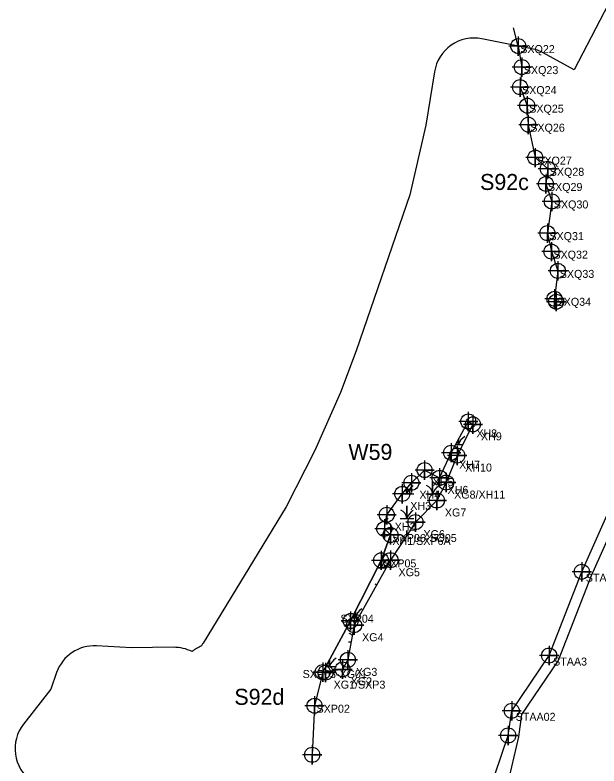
# Model space of a CAD drawing. Extents: x 1253697 to 1278588, y 912189 to 981699.
# Drawn here: x 1253847 to 1254577, y 954967 to 955905 of the extents above; entities that cross this region are included whole.
import ezdxf

# ---------------------------------------------------------------- set-up
doc = ezdxf.new("R2010")
doc.units = 0
for name, color, linetype in [('Default', 7, 'Continuous'), ('Exist Environmental Wetland Boundary', 7, 'Continuous'), ('Exist Environmental Wetland Boundary Cogo Comment', 7, 'Continuous'), ('Exist Environmental Wetland Boundary Cogo Number', 7, 'Continuous'), ('Exist Environmental Wetland Boundary Cogo Point CELL', 7, 'Continuous'), ('Exist Hydro Jurisdictional Stream or Body of Water Mitigable', 7, 'Continuous'), ('Exist Hydro Jurisdictional Stream or Body of Water Mitigable Cogo Comment', 7, 'Continuous'), ('Exist Hydro Jurisdictional Stream or Body of Water Mitigable Cogo Number', 7, 'Continuous'), ('Exist Hydro Jurisdictional Stream or Body of Water Mitigable Cogo Point CELL', 7, 'Continuous'), ('Exist Hydro Swamp or Marsh', 7, 'Continuous')]:
    doc.layers.add(name, color=color, linetype=linetype)

msp = doc.modelspace()

# ---------------------------------------------------------------- linework, layer by layer
at = {"layer": 'Default'}
msp.add_line((1254492.86, 955862.86), (1254430.48, 955875.23), dxfattribs=at)
msp.add_line((1254492.86, 955862.86), (1254430.48, 955875.23), dxfattribs=at)
for points in [[(1254696.64, 956137.98), (1254679.34, 956093.11), (1254545.8, 955836.6), (1254507.05, 955857.72)], [(1254696.64, 956137.98), (1254679.34, 956093.11), (1254545.8, 955836.6), (1254507.05, 955857.72)], [(1254371.38, 955834.12), (1254360.65, 955767.27), (1254340.62, 955680.3), (1254273.47, 955485.55), (1254253.73, 955433.3), (1254221.57, 955360.82), (1254186.04, 955290.67), (1254082.07, 955120.37)], [(1254371.38, 955834.12), (1254360.65, 955767.27), (1254340.62, 955680.3), (1254273.47, 955485.55), (1254253.73, 955433.3), (1254221.57, 955360.82), (1254186.04, 955290.67), (1254082.07, 955120.37)], [(1254045.19, 955115.2), (1253992.76, 955114.66), (1253948.91, 955117.02)], [(1254045.19, 955115.2), (1253992.76, 955114.66), (1253948.91, 955117.02)], [(1253899.08, 955083.78), (1253891.75, 955063.05), (1253857.58, 955019.14)], [(1253899.08, 955083.78), (1253891.75, 955063.05), (1253857.58, 955019.14)]]:
    msp.add_lwpolyline(points, dxfattribs=at)
for centre, start, end in [((1254420.75, 955826.19), 78.77842, 170.8771), ((1254420.75, 955826.19), 78.77842, 170.8771), ((1254483.12, 955813.81), 61.41368, 78.77842), ((1254483.12, 955813.81), 61.41368, 78.77842), ((1253946.22, 955067.1), 86.9118, 160.51196), ((1253946.22, 955067.1), 86.9118, 160.51196), ((1254099.89, 955071.01), 113.22247, 129.13537), ((1254099.89, 955071.01), 113.22247, 129.13537), ((1254124.75, 955094.31), 148.59736, 153.07059), ((1254124.75, 955094.31), 148.59736, 153.07059), ((1254045.7, 955065.2), 63.09678, 90.5931), ((1254045.7, 955065.2), 63.09678, 90.5931), ((1253897.05, 954988.44), 142.11777, 233.22043), ((1253897.05, 954988.44), 142.11777, 233.22043)]:
    msp.add_arc(centre, 50, start, end, dxfattribs=at)
at = {"layer": 'Exist Environmental Wetland Boundary'}
for points in [[(1254308.65, 955263.05), (1254311.59, 955280.74), (1254331.04, 955306.85), (1254342.46, 955320.63), (1254359.01, 955336.53), (1254377.65, 955326.81), (1254392.11, 955358.23), (1254413.55, 955397.26), (1254419.41, 955393.67), (1254399.65, 955354.73), (1254385.85, 955320.93), (1254374.25, 955298.6), (1254347.55, 955271.5), (1254316.35, 955223.95), (1254270.84, 955142.78), (1254263.09, 955099.51), (1254256.48, 955087.62), (1254231.58, 955084.16)], [(1254231.58, 955084.16), (1254266.5, 955148.05), (1254304.54, 955223.8), (1254316.31, 955255.48), (1254308.65, 955263.05)]]:
    msp.add_lwpolyline(points, dxfattribs=at)
at = {"layer": 'Exist Environmental Wetland Boundary Cogo Point CELL'}
for points in [[(1254413.55, 955409.26), (1254413.55, 955385.26), (1254413.55, 955397.26), (1254425.55, 955397.26), (1254401.55, 955397.26)], [(1254419.41, 955405.67), (1254419.41, 955381.67), (1254419.41, 955393.67), (1254431.41, 955393.67), (1254407.41, 955393.67)], [(1254392.11, 955370.23), (1254392.11, 955346.23), (1254392.11, 955358.23), (1254404.11, 955358.23), (1254380.11, 955358.23)], [(1254399.65, 955366.74), (1254399.65, 955342.74), (1254399.65, 955354.73), (1254411.65, 955354.73), (1254387.65, 955354.73)], [(1254359.01, 955348.53), (1254359.01, 955324.53), (1254359.01, 955336.53), (1254371.01, 955336.53), (1254347.01, 955336.53)], [(1254342.46, 955332.63), (1254342.46, 955308.63), (1254342.46, 955320.63), (1254354.46, 955320.63), (1254330.46, 955320.63)], [(1254377.65, 955338.81), (1254377.65, 955314.81), (1254377.65, 955326.81), (1254389.65, 955326.81), (1254365.65, 955326.81)], [(1254385.85, 955332.93), (1254385.85, 955308.93), (1254385.85, 955320.93), (1254397.85, 955320.93), (1254373.85, 955320.93)], [(1254331.04, 955318.85), (1254331.04, 955294.85), (1254331.04, 955306.85), (1254343.04, 955306.85), (1254319.04, 955306.85)], [(1254374.25, 955310.6), (1254374.25, 955286.6), (1254374.25, 955298.6), (1254386.25, 955298.6), (1254362.25, 955298.6)], [(1254311.59, 955292.74), (1254311.59, 955268.74), (1254311.59, 955280.74), (1254323.59, 955280.74), (1254299.59, 955280.74)], [(1254347.55, 955283.5), (1254347.55, 955259.5), (1254347.55, 955271.5), (1254359.55, 955271.5), (1254335.55, 955271.5)], [(1254308.65, 955275.05), (1254308.65, 955251.05), (1254308.65, 955263.05), (1254320.65, 955263.05), (1254296.65, 955263.05)], [(1254316.35, 955235.95), (1254316.35, 955211.95), (1254316.35, 955223.95), (1254328.35, 955223.95), (1254304.35, 955223.95)], [(1254270.84, 955154.78), (1254270.84, 955130.78), (1254270.84, 955142.78), (1254282.84, 955142.78), (1254258.84, 955142.78)], [(1254263.09, 955111.51), (1254263.09, 955087.51), (1254263.09, 955099.51), (1254275.09, 955099.51), (1254251.09, 955099.51)], [(1254256.48, 955099.62), (1254256.48, 955075.62), (1254256.48, 955087.62), (1254268.48, 955087.62), (1254244.48, 955087.62)], [(1254235.27, 955095.59), (1254235.27, 955071.59), (1254235.27, 955083.59), (1254247.27, 955083.59), (1254223.27, 955083.59)]]:
    msp.add_lwpolyline(points, dxfattribs=at)
for centre in [(1254413.55, 955397.26), (1254419.41, 955393.67), (1254392.11, 955358.23), (1254399.65, 955354.73), (1254359.01, 955336.53), (1254377.65, 955326.81), (1254342.46, 955320.63), (1254385.85, 955320.93), (1254331.04, 955306.85), (1254374.25, 955298.6), (1254311.59, 955280.74), (1254347.55, 955271.5), (1254308.65, 955263.05), (1254316.35, 955223.95), (1254270.84, 955142.78), (1254263.09, 955099.51), (1254256.48, 955087.62), (1254235.27, 955083.59)]:
    msp.add_circle(centre, 9.38, dxfattribs=at)
at = {"layer": 'Exist Hydro Jurisdictional Stream or Body of Water Mitigable'}
msp.add_line((1254476.04, 955866.13), (1254470.1, 955888.74), dxfattribs=at)
for points in [[(1254476.02, 955866.2), (1254476.04, 955866.13), (1254480.47, 955839.91), (1254478.27, 955814.83), (1254487.24, 955791.72), (1254488.58, 955767.97), (1254497.3, 955726.83), (1254512.86, 955712.83), (1254510.61, 955693.9), (1254517.98, 955672.09), (1254512.44, 955632.49), (1254517.48, 955609.4), (1254525.42, 955585.32), (1254521.4, 955550.48), (1254523.47, 955546.85)], [(1254558.2, 953978.81), (1254478.51, 954119.21), (1254445.35, 954200.44), (1254401.39, 954397.58), (1254390.69, 954546.32), (1254394.28, 954639.24), (1254399.81, 954647.94), (1254423.24, 954837.79), (1254430.69, 954897.75), (1254438.43, 954931.33), (1254463.4, 955005.06), (1254467.81, 955035.86), (1254514.59, 955104.88), (1254555.42, 955209.58), (1254595.38, 955299.35), (1254605.12, 955312.03), (1254665.04, 955316.01), (1254675.55, 955326.13), (1254684.89, 955326.24), (1254701.96, 955339.89), (1254705.29, 955339.4), (1254784.78, 955359.37)], [(1254776.66, 955344.08), (1254705.95, 955326.31), (1254704.87, 955326.46), (1254669.22, 955303.4), (1254611.78, 955299.59), (1254606.51, 955292.73), (1254567.29, 955204.62), (1254526.04, 955098.86), (1254480.12, 955031.1), (1254476.13, 955003.24), (1254458.85, 954928.27), (1254451.11, 954894.68), (1254443.67, 954834.73), (1254420.23, 954644.88), (1254414.71, 954636.18), (1254411.12, 954543.25), (1254421.82, 954394.51), (1254465.78, 954197.38), (1254498.94, 954116.15), (1254578.62, 953975.74)], [(1254316.31, 955255.48), (1254304.54, 955223.8), (1254266.5, 955148.05), (1254231.58, 955084.16), (1254221.43, 955042.23), (1254218.46, 954980.91)]]:
    msp.add_lwpolyline(points, dxfattribs=at)
at = {"layer": 'Exist Hydro Jurisdictional Stream or Body of Water Mitigable Cogo Point CELL'}
for points in [[(1254476.04, 955878.13), (1254476.04, 955854.13), (1254476.04, 955866.13), (1254488.04, 955866.13), (1254464.04, 955866.13)], [(1254480.47, 955851.91), (1254480.47, 955827.91), (1254480.47, 955839.91), (1254492.47, 955839.91), (1254468.47, 955839.91)], [(1254478.27, 955826.83), (1254478.27, 955802.83), (1254478.27, 955814.83), (1254490.27, 955814.83), (1254466.27, 955814.83)], [(1254487.24, 955803.72), (1254487.24, 955779.72), (1254487.24, 955791.72), (1254499.24, 955791.72), (1254475.24, 955791.72)], [(1254488.58, 955779.97), (1254488.58, 955755.97), (1254488.58, 955767.97), (1254500.58, 955767.97), (1254476.58, 955767.97)], [(1254497.3, 955738.83), (1254497.3, 955714.83), (1254497.3, 955726.83), (1254509.3, 955726.83), (1254485.3, 955726.83)], [(1254512.86, 955724.83), (1254512.86, 955700.83), (1254512.86, 955712.83), (1254524.86, 955712.83), (1254500.86, 955712.83)], [(1254510.61, 955705.9), (1254510.61, 955681.9), (1254510.61, 955693.9), (1254522.61, 955693.9), (1254498.61, 955693.9)], [(1254517.98, 955684.09), (1254517.98, 955660.09), (1254517.98, 955672.09), (1254529.98, 955672.09), (1254505.98, 955672.09)], [(1254512.44, 955644.49), (1254512.44, 955620.49), (1254512.44, 955632.49), (1254524.44, 955632.49), (1254500.44, 955632.49)], [(1254517.48, 955621.4), (1254517.48, 955597.4), (1254517.48, 955609.4), (1254529.48, 955609.4), (1254505.48, 955609.4)], [(1254525.42, 955597.32), (1254525.42, 955573.32), (1254525.42, 955585.32), (1254537.42, 955585.32), (1254513.42, 955585.32)], [(1254521.4, 955562.48), (1254521.4, 955538.48), (1254521.4, 955550.48), (1254533.4, 955550.48), (1254509.4, 955550.48)], [(1254523.47, 955558.85), (1254523.47, 955534.85), (1254523.47, 955546.85), (1254535.47, 955546.85), (1254511.47, 955546.85)], [(1254316.31, 955267.48), (1254316.31, 955243.48), (1254316.31, 955255.48), (1254328.31, 955255.48), (1254304.31, 955255.48)], [(1254304.54, 955235.8), (1254304.54, 955211.8), (1254304.54, 955223.8), (1254316.54, 955223.8), (1254292.54, 955223.8)], [(1254555.42, 955221.58), (1254555.42, 955197.58), (1254555.42, 955209.58), (1254567.42, 955209.58), (1254543.42, 955209.58)], [(1254266.5, 955160.05), (1254266.5, 955136.05), (1254266.5, 955148.05), (1254278.5, 955148.05), (1254254.5, 955148.05)], [(1254514.59, 955116.88), (1254514.59, 955092.88), (1254514.59, 955104.88), (1254526.59, 955104.88), (1254502.59, 955104.88)], [(1254231.58, 955096.16), (1254231.58, 955072.16), (1254231.58, 955084.16), (1254243.58, 955084.16), (1254219.58, 955084.16)], [(1254221.43, 955054.23), (1254221.43, 955030.23), (1254221.43, 955042.23), (1254233.43, 955042.23), (1254209.43, 955042.23)], [(1254467.81, 955047.86), (1254467.81, 955023.86), (1254467.81, 955035.86), (1254479.81, 955035.86), (1254455.81, 955035.86)], [(1254463.4, 955017.06), (1254463.4, 954993.06), (1254463.4, 955005.06), (1254475.4, 955005.06), (1254451.4, 955005.06)], [(1254218.46, 954992.91), (1254218.46, 954968.91), (1254218.46, 954980.91), (1254230.46, 954980.91), (1254206.46, 954980.91)]]:
    msp.add_lwpolyline(points, dxfattribs=at)
for centre in [(1254476.04, 955866.13), (1254480.47, 955839.91), (1254478.27, 955814.83), (1254487.24, 955791.72), (1254488.58, 955767.97), (1254497.3, 955726.83), (1254512.86, 955712.83), (1254510.61, 955693.9), (1254517.98, 955672.09), (1254512.44, 955632.49), (1254517.48, 955609.4), (1254525.42, 955585.32), (1254521.4, 955550.48), (1254523.47, 955546.85), (1254316.31, 955255.48), (1254304.54, 955223.8), (1254555.42, 955209.58), (1254266.5, 955148.05), (1254514.59, 955104.88), (1254231.58, 955084.16), (1254221.43, 955042.23), (1254467.81, 955035.86), (1254463.4, 955005.06), (1254218.46, 954980.91)]:
    msp.add_circle(centre, 9.38, dxfattribs=at)
at = {"layer": 'Exist Hydro Swamp or Marsh'}
for p, q in [((1254310.8, 955276), (1254313.23, 955276)), ((1254312.49, 955245.22), (1254313.23, 955245.22)), ((1254328.23, 955245.22), (1254330.31, 955245.22)), ((1254263.82, 955122.1), (1254267.13, 955122.1))]:
    msp.add_line(p, q, dxfattribs=at)
for points in [[(1254397.66, 955368.34), (1254401.24, 955368.34), (1254401.24, 955374.85)], [(1254401.24, 955374.85), (1254401.24, 955368.34), (1254406.55, 955368.34)], [(1254360.43, 955306.78), (1254369.04, 955306.78), (1254369.04, 955322.56), (1254369.04, 955306.78), (1254377.64, 955306.78)], [(1254330.99, 955306.78), (1254336.83, 955306.78), (1254336.83, 955313.84)], [(1254336.83, 955313.84), (1254336.83, 955306.78), (1254345.43, 955306.78)], [(1254328.23, 955276), (1254336.83, 955276), (1254336.83, 955291.78), (1254336.83, 955276), (1254345.43, 955276)], [(1254336.83, 955255.17), (1254336.83, 955261), (1254336.83, 955255.17)], [(1254299.84, 955214.44), (1254304.63, 955214.44), (1254304.63, 955224.05)], [(1254304.63, 955224.05), (1254304.63, 955214.44), (1254311.02, 955214.44)], [(1254268.93, 955152.88), (1254272.43, 955152.88), (1254272.43, 955159.85)], [(1254272.43, 955159.85), (1254272.43, 955152.88), (1254276.5, 955152.88)], [(1254235.49, 955091.32), (1254240.22, 955091.32), (1254240.22, 955099.97)], [(1254240.22, 955099.97), (1254240.22, 955091.32), (1254248.82, 955091.32)]]:
    msp.add_lwpolyline(points, dxfattribs=at)
for centre, radius, start, end in [((1254419.48, 955362.28), 19.22, 122.12745, 161.62219), ((1254388.97, 955367.45), 12.3, 4.14034, 25.44472), ((1254388.97, 955336.67), 12.3, 53.40228, 67.53497), ((1254355.08, 955300.72), 19.22, 122.12745, 161.62219), ((1254356.77, 955305.89), 12.3, 4.14034, 67.53497), ((1254387.28, 955300.72), 19.22, 122.12745, 161.62219), ((1254324.57, 955305.89), 12.3, 4.14034, 29.52014), ((1254324.57, 955275.11), 12.3, 4.14034, 67.53497), ((1254355.08, 955269.94), 19.22, 122.12745, 161.62219), ((1254356.77, 955275.11), 12.3, 64.57657, 67.53497), ((1254324.57, 955244.33), 12.3, 36.20706, 67.53497), ((1254292.36, 955213.55), 12.3, 4.14034, 32.62955), ((1254322.87, 955208.38), 19.22, 122.12745, 161.62219), ((1254292.36, 955182.77), 12.3, 57.0682, 67.53497), ((1254290.67, 955146.82), 19.22, 122.12745, 161.62219), ((1254260.16, 955151.99), 12.3, 4.14034, 26.13565), ((1254260.16, 955121.21), 12.3, 46.79098, 67.53497), ((1254258.47, 955085.26), 19.22, 122.12745, 161.62219), ((1254227.96, 955090.43), 12.3, 4.14034, 31.13656)]:
    msp.add_arc(centre, radius, start, end, dxfattribs=at)

# ---------------------------------------------------------------- texts
at = {"layer": 'Exist Environmental Wetland Boundary Cogo Comment'}
for s, p in [('XH8', (1254423.55, 955377.26)), ('XH9', (1254429.41, 955373.67)), ('XH7', (1254402.11, 955338.23)), ('XH10', (1254409.65, 955334.73)), ('XH5', (1254369.01, 955316.53)), ('XH6', (1254387.65, 955306.81)), ('XH4', (1254352.46, 955300.63)), ('XG8/XH11', (1254395.85, 955300.93)), ('XH3', (1254341.04, 955286.85)), ('XG7', (1254384.25, 955278.6)), ('XH2', (1254321.59, 955260.74)), ('XG6', (1254357.55, 955251.5)), ('XH1/SXP6A', (1254318.65, 955243.05)), ('XG5', (1254326.35, 955203.95)), ('XG4', (1254280.84, 955122.78)), ('XG3', (1254273.09, 955079.51)), ('XG1/SXP3', (1254245.27, 955063.59)), ('XG2', (1254266.48, 955067.62))]:
    msp.add_text(s, height=10, dxfattribs=at).set_placement(p)
at = {"layer": 'Exist Environmental Wetland Boundary Cogo Number'}
msp.add_text('W59', height=20, dxfattribs=at).set_placement((1254263.69, 955349.26))
at = {"layer": 'Exist Hydro Jurisdictional Stream or Body of Water Mitigable Cogo Comment'}
for s, p in [('SXQ22', (1254478.54, 955857.38)), ('SXQ23', (1254482.97, 955831.16)), ('SXQ24', (1254480.77, 955806.08)), ('SXQ25', (1254489.74, 955782.97)), ('SXQ26', (1254491.08, 955759.22)), ('SXQ27', (1254499.8, 955718.08)), ('SXQ28', (1254515.36, 955704.08)), ('SXQ29', (1254513.11, 955685.15)), ('SXQ30', (1254520.48, 955663.34)), ('SXQ31', (1254514.94, 955623.74)), ('SXQ32', (1254519.98, 955600.65)), ('SXQ33', (1254527.92, 955576.57)), ('SXQ34', (1254523.9, 955541.73)), ('SXP06-SO05', (1254318.81, 955246.73)), ('SXP05', (1254307.04, 955215.05)), ('STAA04', (1254560.42, 955197.08)), ('SXP04', (1254253.78, 955145.98)), ('STAA3', (1254519.59, 955092.38)), ('SXP03-XG01', (1254206.53, 955076.83)), ('SXP02', (1254223.93, 955033.48)), ('STAA02', (1254472.81, 955023.36))]:
    msp.add_text(s, height=10, dxfattribs=at).set_placement(p)
at = {"layer": 'Exist Hydro Jurisdictional Stream or Body of Water Mitigable Cogo Number'}
for s, p in [('S92c', (1254428.31, 955686.39)), ('S92d', (1254121.21, 955043.33))]:
    msp.add_text(s, height=20, dxfattribs=at).set_placement(p)

doc.saveas('drawing.dxf')
